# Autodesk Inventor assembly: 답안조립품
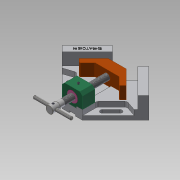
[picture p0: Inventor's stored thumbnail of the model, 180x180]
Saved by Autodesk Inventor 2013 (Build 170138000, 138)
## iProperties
Created: 2019-04
Part Number: 답안조립품
Document SubType Name: Assembly
Designer: Administrator
Author: Administrator
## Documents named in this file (11)
- C:\Users\Administrator\Desktop\490407v1031\답안조립품.iam
- C:\Users\Administrator\Desktop\490407v1031\본체.ipt
- C:\Users\Administrator\Desktop\490407v1031\리드스크류.ipt
- C:\Users\Administrator\Desktop\490407v1031\멈춤나사 M4x5.ipt
- C:\Users\Administrator\Desktop\490407v1031\멈춤나사 M4x10.ipt
- C:\Users\Administrator\Desktop\490407v1031\볼트 M4x16.ipt
- C:\Users\Administrator\Desktop\490407v1031\부시.ipt
- C:\Users\Administrator\Desktop\490407v1031\서포트.ipt
- C:\Users\Administrator\Desktop\490407v1031\조.ipt
- C:\Users\Administrator\Desktop\490407v1031\평행 핀 2.5x24.ipt
- C:\Users\Administrator\Desktop\490407v1031\핸들.ipt
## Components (1 placed, 1 different names)
1. 핸들:1
